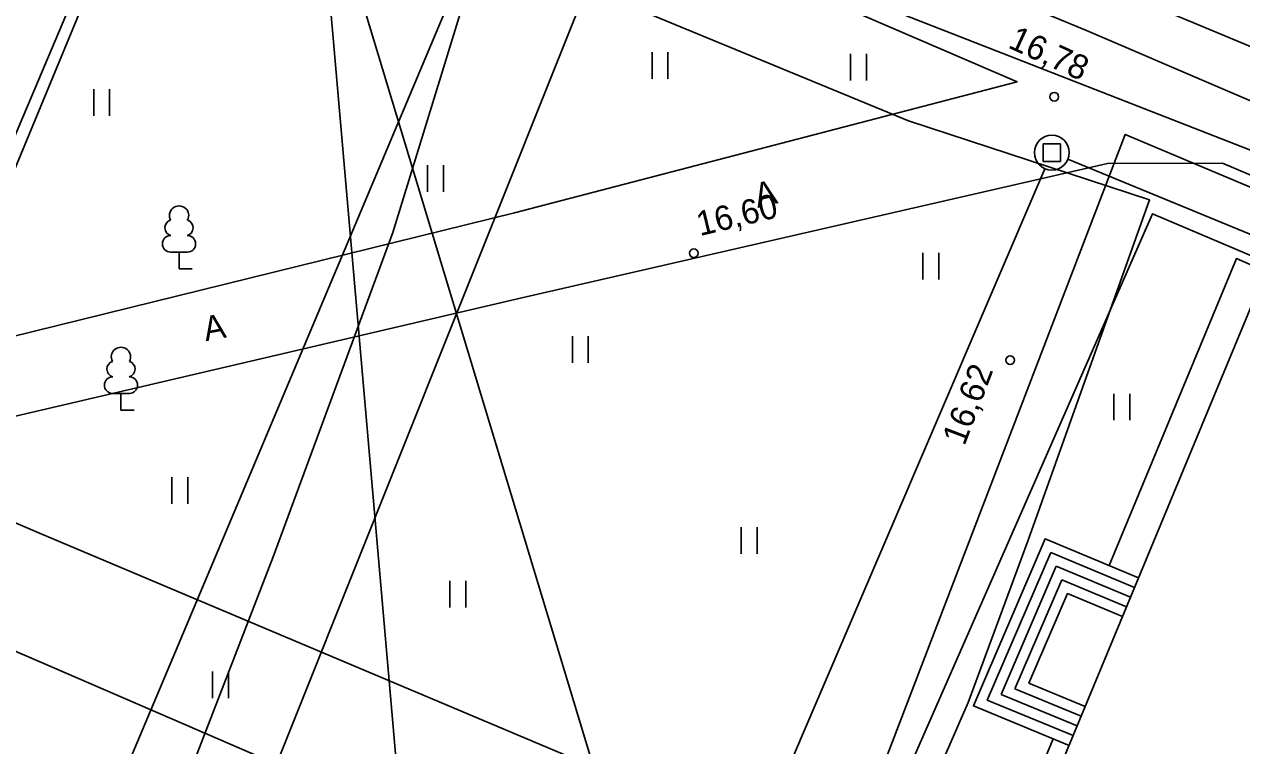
# Model space of a CAD drawing. Extents: x 713540 to 713867, y 6589774 to 6590061.
# Drawn here: x 713614.29 to 713649.11, y 6589915.75 to 6589936.39 of the extents above; entities that cross this region are included whole.
import ezdxf

# ---------------------------------------------------------------- set-up
doc = ezdxf.new("R2010")
doc.units = 0
for name, color, linetype in [('DKAEV', 7, 'Continuous'), ('HALJASTUS', 7, 'Continuous'), ('HOONE', 7, 'Continuous'), ('HOONEDET', 7, 'Continuous'), ('KORGUS', 7, 'Continuous'), ('KPKAABEL', 7, 'Continuous'), ('KTRASS', 7, 'Continuous'), ('MPKAABEL', 7, 'Continuous'), ('PUU', 7, 'Continuous'), ('SITRASS', 7, 'Continuous'), ('TEE', 7, 'Continuous'), ('TTRASS', 7, 'Continuous'), ('VTRASS', 7, 'Continuous'), ('Слой 1', 7, 'Continuous')]:
    doc.layers.add(name, color=color, linetype=linetype)

msp = doc.modelspace()

# ---------------------------------------------------------------- linework, layer by layer
at = {"layer": 'DKAEV'}
for p, q in [((713643.43, 6589932.47), (713643.43, 6589932.97)), ((713643.43, 6589932.97), (713643.93, 6589932.97)), ((713643.93, 6589932.97), (713643.93, 6589932.47)), ((713643.93, 6589932.47), (713643.43, 6589932.47))]:
    msp.add_line(p, q, dxfattribs=at)
msp.add_circle((713643.68, 6589932.72), 0.5, dxfattribs=at)
at = {"layer": 'HALJASTUS'}
for p, q in [((713632.242, 6589935.598), (713632.242, 6589934.837)), ((713632.697, 6589935.598), (713632.697, 6589934.837)), ((713637.919, 6589935.545), (713637.919, 6589934.784)), ((713638.374, 6589935.545), (713638.374, 6589934.784)), ((713616.272, 6589934.537), (713616.272, 6589933.776)), ((713616.727, 6589934.537), (713616.727, 6589933.776)), ((713625.822, 6589932.363), (713625.822, 6589931.602)), ((713626.277, 6589932.363), (713626.277, 6589931.602)), ((713639.993, 6589929.85), (713639.993, 6589929.089)), ((713640.448, 6589929.85), (713640.448, 6589929.089)), ((713629.965, 6589927.464), (713629.965, 6589926.702)), ((713630.42, 6589927.464), (713630.42, 6589926.702)), ((713645.457, 6589925.82), (713645.457, 6589925.059)), ((713645.912, 6589925.82), (713645.912, 6589925.059)), ((713618.504, 6589923.433), (713618.504, 6589922.672)), ((713618.959, 6589923.433), (713618.959, 6589922.672)), ((713634.793, 6589922.002), (713634.793, 6589921.24)), ((713635.248, 6589922.002), (713635.248, 6589921.24)), ((713626.463, 6589920.464), (713626.463, 6589919.703)), ((713626.918, 6589920.464), (713626.918, 6589919.703)), ((713619.671, 6589917.865), (713619.671, 6589917.104)), ((713620.127, 6589917.865), (713620.127, 6589917.104))]:
    msp.add_line(p, q, dxfattribs=at)
msp.add_lwpolyline([(713616.805, 6589939.809), (713613.958, 6589933.059)], dxfattribs=at)
at = {"layer": 'HOONE'}
for points in [[(713644.142, 6589932.53), (713676.393, 6589919.242), (713683.27, 6589916.408)], [(713621.704, 6589881.367), (713643.483, 6589932.26)], [(713671.512, 6589913.992), (713669.17, 6589916.906), (713669.781, 6589918.159), (713652.119, 6589925.348), (713652.861, 6589927.138), (713649.497, 6589928.594), (713640.819, 6589907.673)], [(713644.172, 6589915.756), (713641.437, 6589916.891), (713643.489, 6589921.664), (713646.162, 6589920.555)]]:
    msp.add_lwpolyline(points, dxfattribs=at)
at = {"layer": 'HOONEDET'}
for p, q in [((713641.832, 6589917.051), (713643.648, 6589921.273)), ((713643.648, 6589921.273), (713646.047, 6589920.278)), ((713642.228, 6589917.212), (713643.807, 6589920.883)), ((713643.807, 6589920.883), (713645.932, 6589920.001)), ((713642.624, 6589917.373), (713643.965, 6589920.492)), ((713643.965, 6589920.492), (713645.817, 6589919.724)), ((713643.019, 6589917.533), (713644.124, 6589920.101)), ((713644.124, 6589920.101), (713645.702, 6589919.447)), ((713644.516, 6589916.587), (713642.624, 6589917.373)), ((713644.631, 6589916.864), (713643.019, 6589917.533)), ((713644.286, 6589916.033), (713641.832, 6589917.051)), ((713644.401, 6589916.31), (713642.228, 6589917.212))]:
    msp.add_line(p, q, dxfattribs=at)
msp.add_lwpolyline([(713643.718, 6589915.944), (713640.045, 6589907.089), (713649.308, 6589903.247), (713651.748, 6589909.484), (713660.49, 6589905.59), (713662.88, 6589902.4)], dxfattribs=at)
at = {"layer": 'KORGUS'}
for centre in [(713643.75, 6589934.32), (713633.44, 6589929.84), (713642.49, 6589926.78)]:
    msp.add_circle(centre, 0.125, dxfattribs=at)
at = {"layer": 'KPKAABEL'}
msp.add_lwpolyline([(713539.965, 6589980.838), (713552.788, 6589975.379), (713567.02, 6589969.273), (713582.283, 6589962.777), (713617.601, 6589947.676), (713629.099, 6589942.656), (713644.667, 6589936.214), (713656.147, 6589931.294), (713657.314, 6589931.177), (713661.667, 6589932.013), (713662.753, 6589932.107), (713664.149, 6589932.005), (713666.08, 6589931.349), (713666.349, 6589931.058), (713668.526, 6589927.166), (713675.247, 6589923.087), (713676.674, 6589921.464), (713677.591, 6589920.422), (713678.393, 6589919.51), (713687.845, 6589913.651)], dxfattribs=at)
at = {"layer": 'KTRASS'}
msp.add_line((713618.35, 6589955.601), (713632.529, 6589908.642), dxfattribs=at)
at = {"layer": 'MPKAABEL'}
for points in [[(713539.965, 6589982.441), (713561.72, 6589973.13), (713605.28, 6589954.12), (713658.94, 6589931.77), (713655.667, 6589923.88)], [(713636.109, 6589977.923), (713632.516, 6589979.71), (713628.954, 6589978.46), (713624.941, 6589968.562), (713624.988, 6589963.846), (713624.228, 6589955.304), (713624.309, 6589951.452), (713624.444, 6589944.99), (713624.264, 6589942.119), (713627.907, 6589940.465), (713624.829, 6589930.433), (713621.405, 6589921.156), (713617.009, 6589909.766)], [(713539.965, 6589974.853), (713543.131, 6589973.53), (713546.108, 6589972.287), (713566.322, 6589963.707), (713573.773, 6589960.702), (713592.786, 6589952.579), (713613.42, 6589943.422), (713617.199, 6589942.481), (713626.863, 6589938.886), (713639.576, 6589933.635), (713646.471, 6589931.372), (713643, 6589921.63), (713641.284, 6589916.978), (713637.701, 6589908.759), (713636.487, 6589904.472), (713637.263, 6589902.886), (713641.82, 6589902.37), (713645.539, 6589901.01), (713644.167, 6589896.896), (713647.29, 6589895.882), (713648.871, 6589896.241)]]:
    msp.add_lwpolyline(points, dxfattribs=at)
at = {"layer": 'PUU'}
for p, q in [((713618.952, 6589929.872), (713618.472, 6589929.872)), ((713618.712, 6589929.397), (713618.712, 6589929.872)), ((713619.092, 6589929.397), (713618.712, 6589929.397)), ((713617.291, 6589925.828), (713616.811, 6589925.828)), ((713617.051, 6589925.353), (713617.051, 6589925.828)), ((713617.431, 6589925.353), (713617.051, 6589925.353))]:
    msp.add_line(p, q, dxfattribs=at)
for centre, radius, start, end in [((713618.712, 6589930.917), 0.277, 332.5799, 207.4201), ((713618.541, 6589930.57), 0.233, 109.0217, 253.1415), ((713618.882, 6589930.57), 0.233, 286.8508, 70.9859), ((713618.474, 6589930.11), 0.238, 90.0016, 269.3953), ((713618.949, 6589930.11), 0.238, 270.6047, 89.9984), ((713617.051, 6589926.873), 0.277, 332.5799, 207.4201), ((713616.881, 6589926.526), 0.233, 109.0217, 253.1415), ((713617.221, 6589926.526), 0.233, 286.8508, 70.9859), ((713616.814, 6589926.066), 0.238, 90.0016, 269.3953), ((713617.289, 6589926.066), 0.238, 270.6047, 89.9984)]:
    msp.add_arc(centre, radius, start, end, dxfattribs=at)
at = {"layer": 'SITRASS'}
for points in [[(713660.862, 6589928.302), (713622.483, 6589943.3), (713578.011, 6589961.167)], [(713680.76, 6589850.01), (713672.23, 6589848.51), (713669.283, 6589865.987), (713667.62, 6589875.84), (713665.21, 6589875.309), (713665.174, 6589875.301), (713663.67, 6589874.97), (713661.62, 6589885.51), (713653.61, 6589896.45), (713649.76, 6589901.81), (713649.429, 6589901.945), (713648.305, 6589902.402), (713638.16, 6589906.53), (713639.91, 6589911.24), (713638.2, 6589911.92), (713614.722, 6589921.827), (713596.94, 6589929.45), (713589.631, 6589932.637), (713589.097, 6589932.87), (713558.329, 6589946.285), (713549.9, 6589949.96), (713539.965, 6589954.262)], [(713622.526, 6589942.802), (713625.02, 6589914.21), (713630.01, 6589903.07), (713639.36, 6589886.76), (713642.3, 6589872.04), (713652.19, 6589865.47), (713653.052, 6589864.917), (713657.52, 6589862.05), (713661.076, 6589847.8), (713664.28, 6589834.96), (713666.33, 6589831.93), (713670.966, 6589832.394), (713671.39, 6589832.436), (713687.742, 6589834.073), (713694.81, 6589834.78), (713711.155, 6589837.134), (713711.376, 6589837.166), (713715.85, 6589837.81)], [(713638.2, 6589911.92), (713646.56, 6589930.97), (713672.28, 6589920.04), (713673.742, 6589918.058), (713674.353, 6589917.232), (713684.25, 6589903.82), (713685.11, 6589899.99), (713694.473, 6589901.366), (713697.757, 6589901.848), (713704.78, 6589902.88), (713705.47, 6589904.42), (713707.4, 6589905.83), (713709.059, 6589905.94)]]:
    msp.add_lwpolyline(points, dxfattribs=at)
at = {"layer": 'TEE'}
for points in [[(713574.899, 6589963.436), (713590.337, 6589957.176), (713603.764, 6589951.419), (713623.637, 6589942.963), (713642.688, 6589934.75), (713628.305, 6589930.999), (713599.405, 6589923.875), (713597.72, 6589924.58), (713596.12, 6589930.12)], [(713672.463, 6589922.262), (713648.565, 6589932.421), (713645.27, 6589932.41), (713628.521, 6589928.56), (713605.988, 6589923.296), (713605.17, 6589921.68), (713613.69, 6589917.32), (713613.08, 6589916.21), (713604.26, 6589920.47), (713600, 6589921.07), (713587.083, 6589926.544), (713569.619, 6589934.182), (713565.934, 6589935.405), (713565.316, 6589935.654), (713563.338, 6589936.228), (713561.999, 6589936.133), (713560.468, 6589935.495), (713559.188, 6589934.236), (713557.045, 6589923.518), (713553.905, 6589910.439)], [(713670.794, 6589918.24), (713662.935, 6589921.9), (713653.144, 6589925.885), (713653.822, 6589927.55), (713648.961, 6589929.687), (713645.318, 6589920.905)]]:
    msp.add_lwpolyline(points, dxfattribs=at)
at = {"layer": 'TTRASS'}
for points in [[(713620.04, 6589911.29), (713621.5, 6589915.22), (713632.9, 6589943.77)], [(713594.43, 6589927.17), (713595.41, 6589926.49), (713615.482, 6589917.82), (713621.5, 6589915.22)]]:
    msp.add_lwpolyline(points, dxfattribs=at)
at = {"layer": 'VTRASS'}
msp.add_lwpolyline([(713630.143, 6589945.841), (713616.373, 6589913.119), (713616.392, 6589913.021), (713600.41, 6589874.28), (713604.57, 6589872.55)], dxfattribs=at)
at = {"layer": 'Слой 1'}
for points in [[(713573.6, 6589964.85), (713619.06, 6589944.46), (713608.85, 6589919.78), (713613.96, 6589917.31), (713610.41, 6589911.64), (713607.67, 6589912.62), (713560.07, 6589933.92)], [(713682.51, 6589917.77), (713690.33, 6589877.18), (713657.78, 6589870.72), (713657.67, 6589868.71), (713640.88, 6589865.96), (713635.67, 6589892.95), (713631.47, 6589895.07), (713633.95, 6589902.38), (713645.78, 6589933.24)]]:
    msp.add_lwpolyline(points, close=True, dxfattribs=at)

# ---------------------------------------------------------------- texts
at = {"layer": 'KORGUS'}
for s, rotation, p in [('16,78', 335.4014, (713642.396, 6589935.738)), ('16,60', 13.6097, (713633.611, 6589930.329)), ('16,62', 69.1666, (713641.18, 6589924.306))]:
    msp.add_text(s, height=0.7, rotation=rotation, dxfattribs=at).set_placement(p)
at = {"layer": 'TEE'}
for rotation, p in [(13.2012, (713635.26, 6589931.135)), (10.4324, (713619.476, 6589927.322))]:
    msp.add_text('A', height=0.7, rotation=rotation, dxfattribs=at).set_placement(p)

doc.saveas('drawing.dxf')
